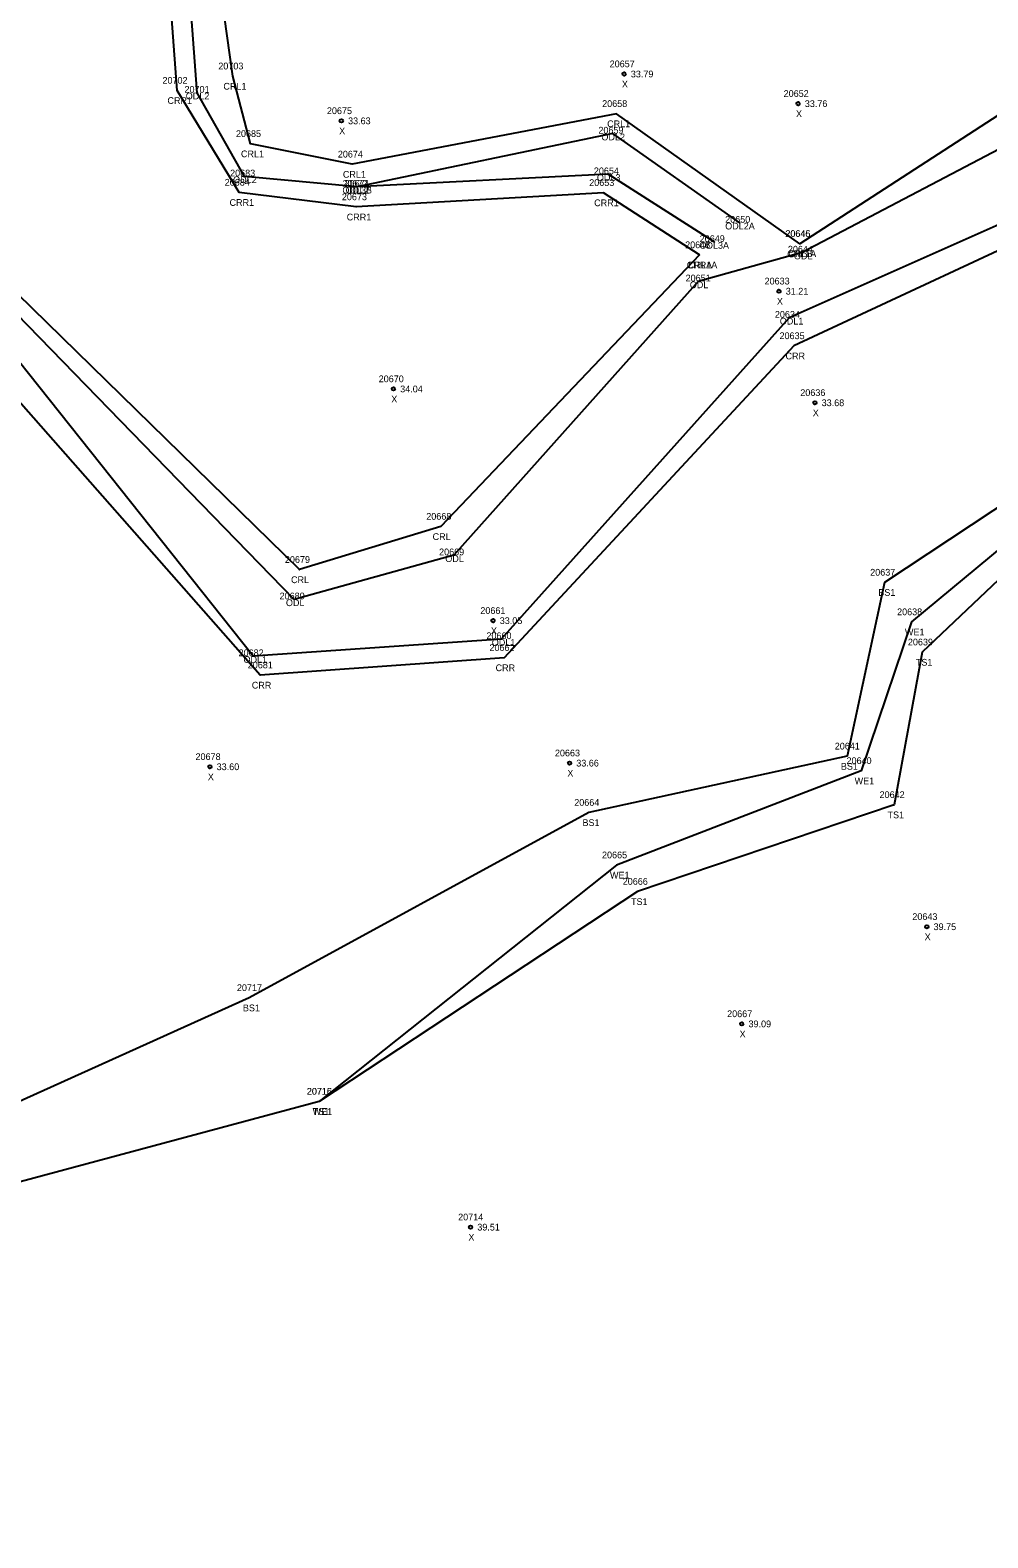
# Model space of a CAD drawing. Extents: x 2445178 to 2446260, y 791158 to 792318.
# Drawn here: x 2445430.8 to 2445572.9, y 791557.1 to 791780.8 of the extents above; entities that cross this region are included whole.
import ezdxf

# ---------------------------------------------------------------- set-up
doc = ezdxf.new("R2010")
doc.units = 0
for name, color, linetype in [('RD_DTM_BkLn2', 7, 'Continuous'), ('RD_EX_H2O', 7, 'Continuous'), ('RD_EX_H2O_txCode', 7, 'Continuous'), ('RD_Sketch8', 7, 'Continuous'), ('RD_SMD_Locator', 7, 'Continuous'), ('RD_SMD_Misc', 7, 'Continuous')]:
    doc.layers.add(name, color=color, linetype=linetype)

msp = doc.modelspace()

# ---------------------------------------------------------------- linework, layer by layer
at = {"layer": 'RD_DTM_BkLn2'}
for points in [[(2445612.18, 791734.98), (2445557.56, 791698.84), (2445552.02, 791673.05), (2445513.68, 791664.7), (2445463.32, 791637.22), (2445363.77, 791592.3), (2445292.26, 791558.82)], [(2445612.18, 791734.98), (2445563.15, 791688.49), (2445558.95, 791665.85), (2445520.9, 791652.98), (2445473.7, 791621.85), (2445363.77, 791592.3)]]:
    msp.add_lwpolyline(points, dxfattribs=at)
at = {"layer": 'RD_EX_H2O'}
for points in [[(2445544.99, 791749.08), (2445517.8, 791768.36), (2445478.59, 791760.86), (2445463.48, 791763.9), (2445460.87, 791773.93), (2445455.89, 791809.54), (2445415.21, 791826.15)], [(2445536.09, 791752.19), (2445517.24, 791765.41), (2445479.3, 791757.52), (2445462.61, 791759.06), (2445455.58, 791771.48), (2445452.95, 791806.64), (2445409.65, 791824.04)], [(2445530.12, 791747.41), (2445515.88, 791756.64), (2445479.19, 791754.53), (2445461.81, 791756.69), (2445452.6, 791771.81), (2445450.18, 791804.36), (2445403.09, 791820.76)], [(2445748.32, 791780.49), (2445701.12, 791774.43), (2445677.09, 791767.59), (2445662.39, 791761.56), (2445644.36, 791766.93), (2445623.55, 791762.71), (2445618.49, 791746.46), (2445607.67, 791748.78), (2445606.64, 791748.27), (2445612.18, 791734.98), (2445561.56, 791692.97), (2445554.1, 791670.89), (2445517.8, 791656.91), (2445473.7, 791621.85), (2445363.77, 791592.3), (2445292.26, 791558.82)], [(2445597.34, 791773), (2445578, 791770.46), (2445544.99, 791749.08)], [(2445598, 791771), (2445580.58, 791766.25), (2445545.35, 791747.76), (2445529.9, 791743.48), (2445493.64, 791702.86), (2445469.99, 791696.32), (2445420.2, 791747.49), (2445408.65, 791738.85), (2445398.22, 791720.47), (2445370.93, 791678.47), (2445333.32, 791699.47), (2445304.17, 791689.05), (2445297.68, 791600.13), (2445290.12, 791566.49)], [(2445600.16, 791766.47), (2445586.11, 791757.06), (2445543.42, 791738.09), (2445500.69, 791690.42), (2445463.87, 791687.89), (2445423.05, 791739.22), (2445412.07, 791732.11), (2445402.24, 791718.7), (2445377.05, 791678.37), (2445370.6, 791674.92), (2445335.15, 791693.03), (2445306.01, 791687.27), (2445304.48, 791597.26), (2445303.65, 791580.6), (2445291.47, 791560.13)], [(2445601.06, 791763.87), (2445588.04, 791754.39), (2445544.11, 791733.92), (2445501.1, 791687.67), (2445464.95, 791685.09), (2445422.11, 791733.61), (2445413.32, 791729.6), (2445404.23, 791718.68), (2445377.21, 791675.18), (2445369.95, 791673.71), (2445335.95, 791691.26), (2445308.99, 791685.23), (2445308.22, 791596.59), (2445306.48, 791581.14), (2445293.31, 791557.11)], [(2445532.27, 791749.33), (2445516.57, 791759.38), (2445479.3, 791757.52)], [(2445530.12, 791747.41), (2445491.74, 791707.13), (2445470.74, 791700.73), (2445420.06, 791750.24), (2445407.82, 791740.44), (2445395.12, 791721.24), (2445370.26, 791681.38), (2445332.86, 791701.82), (2445302.63, 791690.34), (2445292.86, 791599.86), (2445287.21, 791569.74)]]:
    msp.add_lwpolyline(points, dxfattribs=at)
at = {"layer": 'RD_SMD_Locator'}
for centre, radius in [((2445460.87, 791773.93), 0.001), ((2445518.91, 791774.25), 0.25), ((2445452.6, 791771.81), 0.001), ((2445455.58, 791771.48), 0.001), ((2445544.72, 791769.85), 0.25), ((2445476.97, 791767.3), 0.25), ((2445517.8, 791768.36), 0.001), ((2445517.24, 791765.41), 0.001), ((2445463.48, 791763.9), 0.001), ((2445478.59, 791760.86), 0.001), ((2445462.61, 791759.06), 0.001), ((2445516.57, 791759.38), 0.001), ((2445461.81, 791756.69), 0.001), ((2445479.3, 791757.52), 0.001), ((2445479.3, 791757.52), 0.001), ((2445515.88, 791756.64), 0.001), ((2445479.19, 791754.53), 0.001), ((2445536.09, 791752.19), 0.001), ((2445532.27, 791749.33), 0.001), ((2445544.99, 791749.08), 0.001), ((2445544.99, 791749.08), 0.001), ((2445530.12, 791747.41), 0.001), ((2445530.12, 791747.41), 0.001), ((2445545.35, 791747.76), 0.001), ((2445529.9, 791743.48), 0.001), ((2445541.89, 791742.03), 0.25), ((2445543.42, 791738.09), 0.001), ((2445544.11, 791733.92), 0.001), ((2445484.7, 791727.53), 0.25), ((2445547.22, 791725.48), 0.25), ((2445491.74, 791707.13), 0.001), ((2445493.64, 791702.86), 0.001), ((2445470.74, 791700.73), 0.001), ((2445557.56, 791698.84), 0.001), ((2445469.99, 791696.32), 0.001), ((2445499.47, 791693.16), 0.25), ((2445561.56, 791692.97), 0.001), ((2445500.69, 791690.42), 0.001), ((2445563.15, 791688.49), 0.001), ((2445463.87, 791687.89), 0.001), ((2445501.1, 791687.67), 0.001), ((2445464.95, 791685.09), 0.001), ((2445552.02, 791673.05), 0.001), ((2445457.48, 791671.49), 0.25), ((2445510.82, 791672.03), 0.25), ((2445554.1, 791670.89), 0.001), ((2445513.68, 791664.7), 0.001), ((2445558.95, 791665.85), 0.001), ((2445517.8, 791656.91), 0.001), ((2445520.9, 791652.98), 0.001), ((2445563.82, 791647.76), 0.25), ((2445463.32, 791637.22), 0.001), ((2445536.37, 791633.35), 0.25), ((2445473.7, 791621.85), 0.001), ((2445473.7, 791621.85), 0.001), ((2445496.14, 791603.2), 0.25)]:
    msp.add_circle(centre, radius, dxfattribs=at)

# ---------------------------------------------------------------- texts
at = {"layer": 'RD_EX_H2O_txCode'}
for s, p in [('20703', (2445458.72, 791774.93)), ('20702', (2445450.44, 791772.81)), ('20701', (2445453.71, 791771.48)), ('ODL2', (2445453.89, 791770.48)), ('CRL1', (2445459.48, 791771.93)), ('CRR1', (2445451.18, 791769.81)), ('20658', (2445515.66, 791769.36)), ('CRL1', (2445516.4, 791766.36)), ('20685', (2445461.34, 791764.9)), ('20659', (2445515.1, 791765.41)), ('ODL2', (2445515.55, 791764.41)), ('CRL1', (2445462.08, 791761.9)), ('20674', (2445476.45, 791761.86)), ('20683', (2445460.47, 791759.06)), ('CRL1', (2445477.2, 791758.86)), ('20654', (2445514.43, 791759.38)), ('20684', (2445459.67, 791757.69)), ('ODL2', (2445460.92, 791758.06)), ('20672', (2445477.16, 791757.52)), ('20671', (2445477.44, 791757.52)), ('20653', (2445513.74, 791757.64)), ('ODL3', (2445514.88, 791758.38)), ('CRR1', (2445460.39, 791754.69)), ('20673', (2445477.05, 791755.53)), ('ODL3B', (2445477.13, 791756.52)), ('ODL2', (2445477.61, 791756.52)), ('CRR1', (2445514.47, 791754.64)), ('CRR1', (2445477.77, 791752.53)), ('20650', (2445533.91, 791752.19)), ('ODL2A', (2445533.91, 791751.19)), ('20646', (2445542.82, 791750.08)), ('20645', (2445542.85, 791750.08)), ('20647', (2445527.97, 791748.41)), ('20648', (2445527.97, 791748.41)), ('ODL3A', (2445530.09, 791748.33)), ('20649', (2445530.13, 791749.33)), ('20644', (2445543.21, 791747.76)), ('CRL1A', (2445543.11, 791747.08)), ('CRLB', (2445543.29, 791747.08)), ('ODL', (2445544.11, 791746.76)), ('20651', (2445528.04, 791743.48)), ('CRR1A', (2445528.21, 791745.41)), ('CRLA', (2445528.4, 791745.41)), ('ODL', (2445528.66, 791742.48)), ('20634', (2445541.28, 791738.09)), ('ODL1', (2445542.01, 791737.09)), ('20635', (2445541.97, 791734.92)), ('CRR', (2445542.86, 791731.92)), ('20668', (2445489.57, 791708.13)), ('CRL', (2445490.51, 791705.13)), ('20679', (2445468.6, 791701.73)), ('20669', (2445491.47, 791702.86)), ('ODL', (2445492.39, 791701.86)), ('CRL', (2445469.51, 791698.73)), ('20680', (2445467.81, 791696.32)), ('ODL', (2445468.75, 791695.32)), ('20638', (2445559.41, 791693.97)), ('20660', (2445498.49, 791690.42)), ('WE1', (2445560.57, 791690.97)), ('20682', (2445461.73, 791687.89)), ('20662', (2445498.94, 791688.67)), ('ODL1', (2445499.29, 791689.42)), ('ODL1', (2445462.46, 791686.89)), ('20681', (2445463.09, 791686.09)), ('CRR', (2445499.85, 791685.67)), ('CRR', (2445463.69, 791683.09)), ('20640', (2445551.91, 791671.89)), ('WE1', (2445553.11, 791668.89)), ('20665', (2445515.64, 791657.91)), ('WE1', (2445516.82, 791654.91)), ('20715', (2445471.87, 791622.85)), ('WE1', (2445472.72, 791619.85))]:
    msp.add_text(s, height=1, dxfattribs=at).set_placement(p)
at = {"layer": 'RD_Sketch8'}
for s, p in [('20657', (2445516.77, 791775.25)), ('33.79', (2445519.91, 791773.75)), ('X', (2445518.59, 791772.25)), ('20652', (2445542.58, 791770.85)), ('20675', (2445474.83, 791768.3)), ('X', (2445544.41, 791767.85)), ('33.76', (2445545.72, 791769.35)), ('33.63', (2445477.97, 791766.8)), ('X', (2445476.65, 791765.3)), ('20633', (2445539.75, 791743.03)), ('31.21', (2445542.89, 791741.53)), ('X', (2445541.58, 791740.03)), ('20670', (2445482.51, 791728.53)), ('X', (2445484.38, 791725.53)), ('34.04', (2445485.7, 791727.03)), ('20636', (2445545.05, 791726.48)), ('X', (2445546.9, 791723.48)), ('33.68', (2445548.22, 791724.98)), ('20661', (2445497.59, 791694.16)), ('33.05', (2445500.47, 791692.66)), ('X', (2445499.16, 791691.16)), ('20678', (2445455.34, 791672.49)), ('20663', (2445508.65, 791673.03)), ('X', (2445457.17, 791669.49)), ('33.60', (2445458.48, 791670.99)), ('X', (2445510.5, 791670.03)), ('33.66', (2445511.82, 791671.53)), ('20643', (2445561.67, 791648.76)), ('39.75', (2445564.82, 791647.26)), ('X', (2445563.5, 791645.76)), ('20667', (2445534.2, 791634.35)), ('39.09', (2445537.37, 791632.85)), ('X', (2445536.05, 791631.35)), ('20714', (2445494.3, 791604.2)), ('39.51', (2445497.14, 791602.7)), ('X', (2445495.82, 791601.2))]:
    msp.add_text(s, height=1, dxfattribs=at).set_placement(p)
at = {"layer": 'RD_SMD_Misc'}
for s, p in [('20637', (2445555.42, 791699.84)), ('BS1', (2445556.62, 791696.84)), ('20639', (2445561.01, 791689.49)), ('TS1', (2445562.19, 791686.49)), ('20641', (2445550.16, 791674.05)), ('BS1', (2445551.07, 791671.05)), ('20664', (2445511.52, 791665.7)), ('20642', (2445556.81, 791666.85)), ('BS1', (2445512.74, 791662.7)), ('TS1', (2445557.99, 791663.85)), ('20666', (2445518.71, 791653.98)), ('TS1', (2445519.94, 791650.98)), ('20717', (2445461.48, 791638.22)), ('BS1', (2445462.37, 791635.22)), ('20716', (2445471.84, 791622.85)), ('TS1', (2445472.74, 791619.85))]:
    msp.add_text(s, height=1, dxfattribs=at).set_placement(p)

doc.saveas('drawing.dxf')
